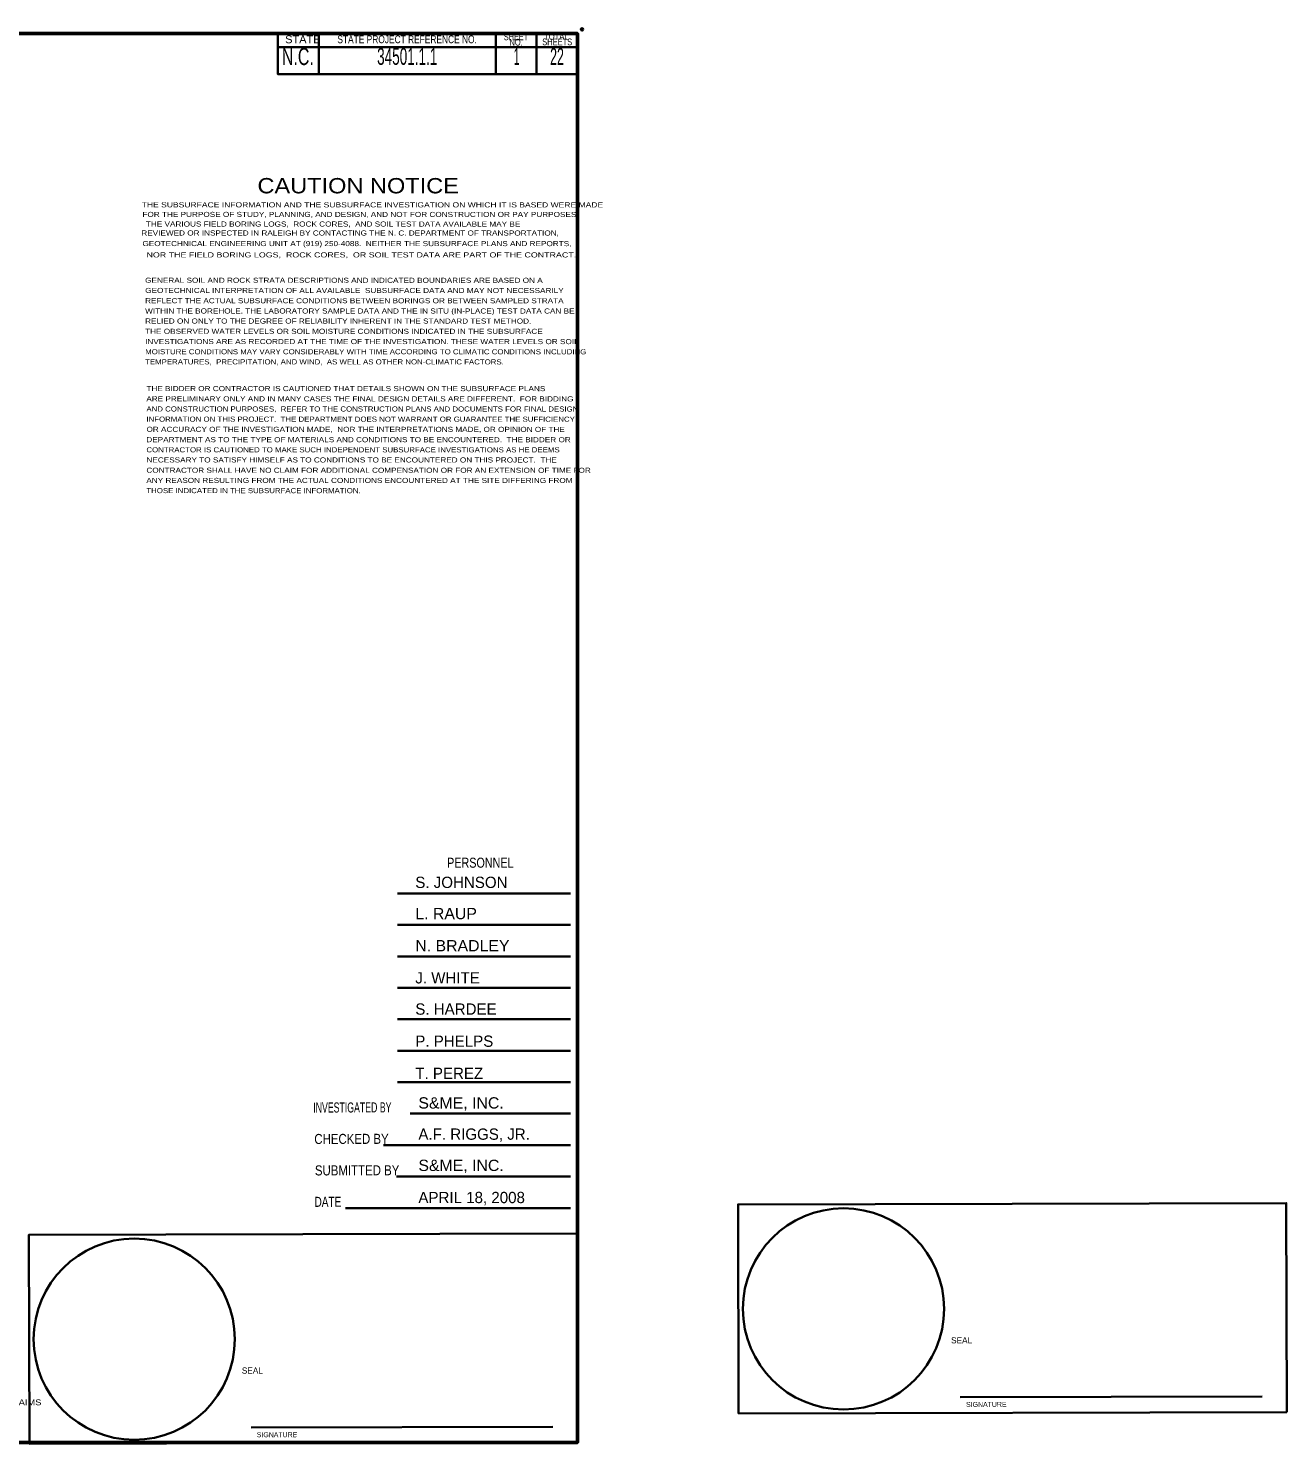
# Model space of a CAD drawing. Extents: x 278712 to 279914, y 171254 to 171792.
# Drawn here: x 278866.5 to 278960.1, y 171476 to 171581.3 of the extents above; entities that cross this region are included whole.
import ezdxf
from ezdxf.enums import TextEntityAlignment as Align

# ---------------------------------------------------------------- set-up
doc = ezdxf.new("R2010")
doc.units = 0
doc.header["$LTSCALE"] = 0.34
doc.header["$PDMODE"] = 32
doc.header["$PDSIZE"] = 0.17
doc.layers.add('23', color=7, linetype='Continuous', lineweight=35)
doc.layers.add('60', color=7, linetype='Continuous', lineweight=35)

msp = doc.modelspace()

# ---------------------------------------------------------------- linework, layer by layer
at = {"layer": '23'}
for p, q in [((278935.8371, 171479.4397), (278958.3011, 171479.4917)), ((278883.0366, 171477.1857), (278905.5006, 171477.2377))]:
    msp.add_line(p, q, dxfattribs=at)
for points in [[(278960.1381, 171478.3352), (278919.3381, 171478.2407), (278919.3021, 171493.7972), (278960.1026, 171493.8912)], [(278907.3376, 171476.0812), (278866.5376, 171475.9867), (278866.5016, 171491.5432), (278907.3021, 171491.6372)]]:
    msp.add_lwpolyline(points, close=True, dxfattribs=at)
for centre in [(278927.1453, 171486.0185), (278874.3448, 171483.7644)]:
    msp.add_circle(centre, 7.488, dxfattribs=at)
at = {"layer": '60'}
for p, q in [((278888.0764, 171580.9495), (278888.0764, 171577.9145)), ((278901.2554, 171580.9495), (278901.2554, 171577.9145)), ((278904.2964, 171580.9495), (278904.2964, 171577.9145)), ((278885.0344, 171579.9405), (278907.3376, 171579.9405)), ((278893.9379, 171516.9367), (278906.8336, 171516.9367)), ((278893.9379, 171514.5967), (278906.8336, 171514.5967)), ((278893.9379, 171512.2567), (278906.8336, 171512.2567)), ((278893.9379, 171509.9167), (278906.8336, 171509.9167)), ((278893.9379, 171507.5767), (278906.8336, 171507.5767)), ((278893.9379, 171505.2367), (278906.8336, 171505.2367)), ((278893.9379, 171502.8967), (278906.8336, 171502.8967)), ((278894.8871, 171500.5567), (278906.8336, 171500.5567)), ((278892.8989, 171498.2117), (278906.8336, 171498.2117)), ((278893.8691, 171495.8747), (278906.8336, 171495.8747)), ((278890.0739, 171493.5257), (278906.8336, 171493.5257))]:
    msp.add_line(p, q, dxfattribs=at)
at = {"layer": '60', "lineweight": 53}
msp.add_lwpolyline([(278756.0874, 171580.9495), (278907.3376, 171580.9495), (278907.3376, 171476.0812), (278756.0874, 171476.0812)], close=True, dxfattribs=at)
at = {"layer": '60'}
msp.add_lwpolyline([(278885.0344, 171580.9495), (278907.3376, 171580.9495), (278907.3376, 171577.9145), (278885.0344, 171577.9145)], close=True, dxfattribs=at)
msp.add_point((278907.6876, 171581.2545), dxfattribs=at)

# ---------------------------------------------------------------- texts
at = {"layer": '23'}
for s, height, p in [('SEAL', 0.4587, (278935.1541, 171483.4537)), ('SEAL', 0.4587, (278882.3536, 171481.1997)), ('SIGNATURE', 0.3744, (278936.2691, 171478.7197)), ('SIGNATURE', 0.3744, (278883.4686, 171476.4657))]:
    msp.add_text(s, height=height, rotation=0.132, dxfattribs=at).set_placement(p)
at = {"layer": '60'}
for s, height, rotation, width, p in [('STATE', 0.5824, 0.015, 1.05, (278886.8979, 171580.2268)), ('STATE PROJECT REFERENCE NO.', 0.5824, 0.015, 0.8, (278894.6598, 171580.2289)), ('SHEET', 0.4992, 0.015, 0.75, (278902.7644, 171580.4557)), ('TOTAL', 0.4992, 0.015, 0.85, (278905.7669, 171580.4847)), ('N.C.', 1.271, 0.015, 0.7, (278886.524, 171578.6068)), ('34501.1.1', 1.255, 0.015, 0.6, (278894.6663, 171578.619)), ('NO.', 0.4992, 0.015, 0.7, (278902.7706, 171580.0536)), ('1', 1.255, 0.015, 0.45, (278902.8075, 171578.6195)), ('SHEETS', 0.4992, 0.015, 0.7, (278905.8322, 171580.0787)), ('22', 1.255, 0.015, 0.55, (278905.8175, 171578.6196)), ('CAUTION NOTICE ', 1.14, 359.992, 1.15, (278891.2602, 171569.0546)), ('THE SUBSURFACE INFORMATION AND THE SUBSURFACE INVESTIGATION ON WHICH IT IS BASED WERE MADE', 0.3798, 359.992, 1.25, (278892.0767, 171568.0097)), ('FOR THE PURPOSE OF STUDY, PLANNING, AND DESIGN, AND NOT FOR CONSTRUCTION OR PAY PURPOSES. ', 0.3798, 359.992, 1.2, (278891.2736, 171567.2954)), ('REVIEWED OR INSPECTED IN RALEIGH BY CONTACTING THE N. C. DEPARTMENT OF TRANSPORTATION, ', 0.3798, 359.992, 1.2, (278890.4995, 171565.9137)), ('GEOTECHNICAL ENGINEERING UNIT AT (919) 250-4088.  NEITHER THE SUBSURFACE PLANS AND REPORTS,', 0.3798, 359.992, 1.2, (278890.9228, 171565.1261)), ('NOTE - BY HAVING REQUESTED THIS INFORMATION THE CONTRACTOR SPECIFICALLY WAIVES ANY CLAIMS', 0.4314, 359.992, 1.2, (278849.1248, 171478.8515))]:
    msp.add_text(s, height=height, rotation=rotation, dxfattribs=dict(at, width=width)).set_placement(p, align=Align.CENTER)
for s, height, rotation, width, p in [('THE VARIOUS FIELD BORING LOGS,  ROCK CORES,  AND SOIL TEST DATA AVAILABLE MAY BE ', 0.3798, 359.992, 1.2, (278875.2111, 171566.5822)), ('NOR THE FIELD BORING LOGS,  ROCK CORES,  OR SOIL TEST DATA ARE PART OF THE CONTRACT.', 0.3798, 359.992, 1.3, (278875.2561, 171564.2872)), ('GENERAL SOIL AND ROCK STRATA DESCRIPTIONS AND INDICATED BOUNDARIES ARE BASED ON A', 0.3798, 359.992, 1.2, (278875.1539, 171562.396)), ('GEOTECHNICAL INTERPRETATION OF ALL AVAILABLE  SUBSURFACE DATA AND MAY NOT NECESSARILY', 0.3798, 359.992, 1.2, (278875.1594, 171561.6375)), ('REFLECT THE ACTUAL SUBSURFACE CONDITIONS BETWEEN BORINGS OR BETWEEN SAMPLED STRATA ', 0.3798, 359.992, 1.2, (278875.1549, 171560.8737)), ('WITHIN THE BOREHOLE. THE LABORATORY SAMPLE DATA AND THE IN SITU (IN-PLACE) TEST DATA CAN BE', 0.3798, 359.992, 1.2, (278875.1549, 171560.1107)), ('RELIED ON ONLY TO THE DEGREE OF RELIABILITY INHERENT IN THE STANDARD TEST METHOD.', 0.3798, 359.992, 1.2, (278875.1549, 171559.3617)), ('THE OBSERVED WATER LEVELS OR SOIL MOISTURE CONDITIONS INDICATED IN THE SUBSURFACE ', 0.3798, 359.992, 1.2, (278875.1549, 171558.599)), ('INVESTIGATIONS ARE AS RECORDED AT THE TIME OF THE INVESTIGATION. THESE WATER LEVELS OR SOIL', 0.3798, 359.992, 1.2, (278875.1549, 171557.835)), ('TEMPERATURES,  PRECIPITATION, AND WIND,  AS WELL AS OTHER NON-CLIMATIC FACTORS.', 0.3798, 359.992, 1.15, (278875.1504, 171556.3232)), ('MOISTURE CONDITIONS MAY VARY CONSIDERABLY WITH TIME ACCORDING TO CLIMATIC CONDITIONS INCLUDING', 0.3798, 359.992, 1.15, (278875.1601, 171557.0765)), ('THE BIDDER OR CONTRACTOR IS CAUTIONED THAT DETAILS SHOWN ON THE SUBSURFACE PLANS', 0.3798, 359.992, 1.2, (278875.2491, 171554.3345)), ('ARE PRELIMINARY ONLY AND IN MANY CASES THE FINAL DESIGN DETAILS ARE DIFFERENT.  FOR BIDDING', 0.3798, 359.992, 1.2, (278875.2439, 171553.5705)), ('AND CONSTRUCTION PURPOSES,  REFER TO THE CONSTRUCTION PLANS AND DOCUMENTS FOR FINAL DESIGN', 0.3798, 359.992, 1.15, (278875.2491, 171552.8172)), ('INFORMATION ON THIS PROJECT.  THE DEPARTMENT DOES NOT WARRANT OR GUARANTEE THE SUFFICIENCY', 0.3798, 359.992, 1.15, (278875.2491, 171552.0587)), ('OR ACCURACY OF THE INVESTIGATION MADE,  NOR THE INTERPRETATIONS MADE, OR OPINION OF THE ', 0.3793, 359.992, 1.2, (278875.2544, 171551.3002)), ('DEPARTMENT AS TO THE TYPE OF MATERIALS AND CONDITIONS TO BE ENCOUNTERED.  THE BIDDER OR', 0.3798, 359.992, 1.2, (278875.2446, 171550.532)), ('CONTRACTOR IS CAUTIONED TO MAKE SUCH INDEPENDENT SUBSURFACE INVESTIGATIONS AS HE DEEMS', 0.3798, 359.992, 1.15, (278875.2499, 171549.7777)), ('NECESSARY TO SATISFY HIMSELF AS TO CONDITIONS TO BE ENCOUNTERED ON THIS PROJECT.  THE', 0.3798, 359.992, 1.2, (278875.2551, 171549.0245)), ('CONTRACTOR SHALL HAVE NO CLAIM FOR ADDITIONAL COMPENSATION OR FOR AN EXTENSION OF TIME FOR', 0.3798, 359.992, 1.2, (278875.2499, 171548.2562)), ('ANY REASON RESULTING FROM THE ACTUAL CONDITIONS ENCOUNTERED AT THE SITE DIFFERING FROM ', 0.3798, 359.992, 1.2, (278875.2456, 171547.4977)), ('THOSE INDICATED IN THE SUBSURFACE INFORMATION.', 0.3796, 359.992, 1.15, (278875.2456, 171546.739)), ('PERSONNEL', 0.7488, 0.132, 0.8, (278897.6389, 171518.8535)), ('INVESTIGATED BY', 0.7488, 0.132, 0.65, (278887.6709, 171500.6337)), ('CHECKED BY', 0.7488, 0.132, 0.85, (278887.7509, 171498.2937)), ('SUBMITTED BY', 0.7488, 0.132, 0.85, (278887.7939, 171495.9537)), ('DATE', 0.7488, 0.132, 0.75, (278887.7619, 171493.6137))]:
    msp.add_text(s, height=height, rotation=rotation, dxfattribs=dict(at, width=width)).set_placement(p)
for s, p in [('S. JOHNSON', (278895.2669, 171517.3505)), ('J. WHITE', (278895.2669, 171510.2435)), ('S. HARDEE', (278895.2669, 171507.9185)), ('P. PHELPS', (278895.2669, 171505.5275)), ('T. PEREZ', (278895.2669, 171503.1365)), ('A.F. RIGGS, JR.', (278895.4971, 171498.6087)), ('APRIL 18, 2008', (278895.4971, 171493.8927))]:
    msp.add_text(s, height=0.84, dxfattribs=at).set_placement(p)
at = {"layer": '60', "width": 1.05}
for s, p in [('L. RAUP', (278895.2669, 171515.0255)), ('N. BRADLEY', (278895.2669, 171512.6345)), ('S&ME, INC.', (278895.4971, 171500.9337)), ('S&ME, INC.', (278895.4971, 171496.2837))]:
    msp.add_text(s, height=0.84, dxfattribs=at).set_placement(p)

doc.saveas('drawing.dxf')
